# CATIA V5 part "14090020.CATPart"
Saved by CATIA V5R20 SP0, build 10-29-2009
Part number: 14090020
Definition: NONE
Nomenclature: 14090020
Source: Unknown
Description: 14090020
Bounding box of the stored display mesh (mm): x -10 to 40, y -59 to 49.1, z -49.1 to 49.1
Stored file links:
  C:\Users\Utente\Desktop\IO LAVORO\3D X SITO CF\X SITO\PLASTICA\RF2\14090020.CATPart
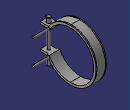
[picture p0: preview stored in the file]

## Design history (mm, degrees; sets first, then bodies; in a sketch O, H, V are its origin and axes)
Body1 "14090020" (main body)
  Solid1: solid without history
